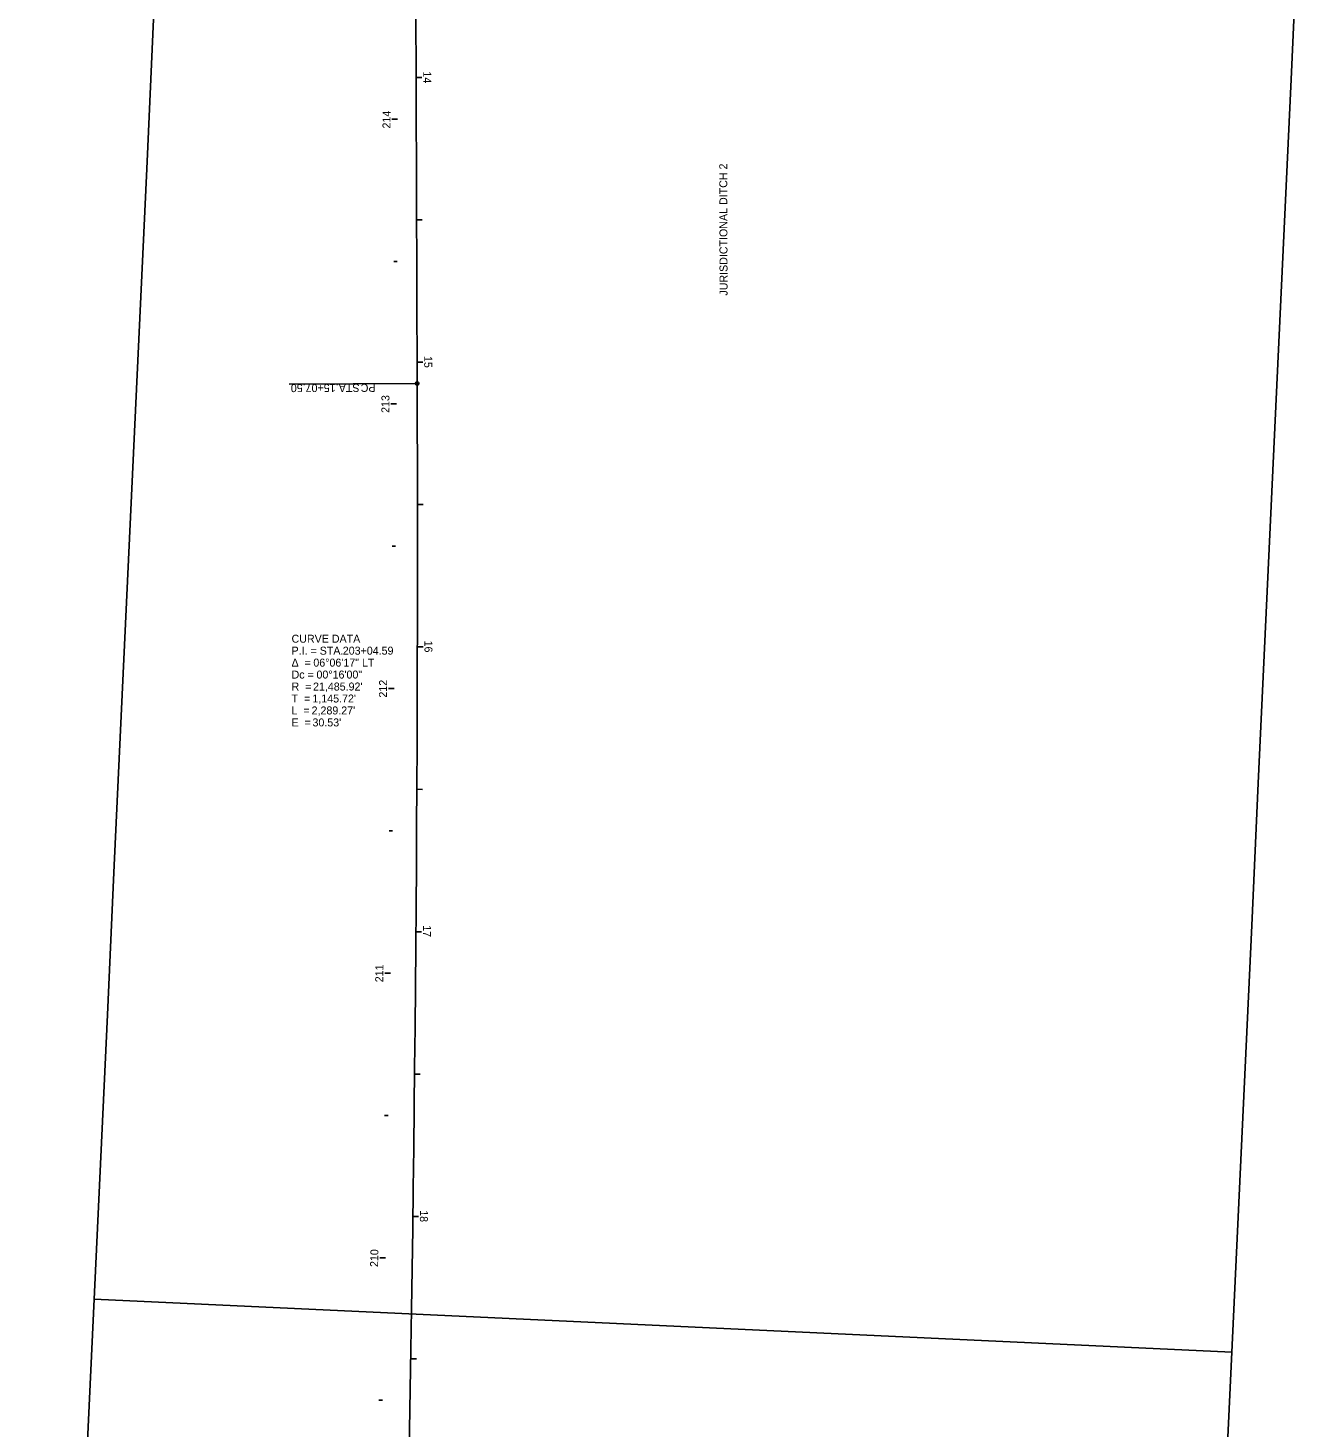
# Model space of a CAD drawing. Extents: x 172043 to 172958, y 249504 to 260295.
# Drawn here: x 172382 to 172828, y 257862.1 to 258353.8 of the extents above; entities that cross this region are included whole.
import ezdxf

# ---------------------------------------------------------------- set-up
doc = ezdxf.new("R2010")
doc.units = 0
for name, color, linetype in [('DR_X_Storm_Sewer', 7, 'Continuous'), ('LT_X_Poles', 7, 'Continuous'), ('PV_X_EOP', 7, 'Continuous'), ('RD_X_Fence', 7, 'Continuous'), ('SC_Scratch1', 7, 'Continuous')]:
    doc.layers.add(name, color=color, linetype=linetype)

msp = doc.modelspace()

# ---------------------------------------------------------------- linework, layer by layer
at = {"layer": 'DR_X_Storm_Sewer'}
for points in [[(172405.19, 257907.39), (172804.75, 257888.81), (172807.08, 257938.76), (172809.4, 257988.7), (172811.72, 258038.65), (172814.04, 258088.6), (172816.37, 258138.54), (172818.69, 258188.49), (172821.01, 258238.43), (172823.34, 258288.38), (172825.66, 258338.33), (172827.98, 258388.27), (172428.41, 258406.85), (172426.09, 258356.91), (172423.77, 258306.96), (172421.44, 258257.02), (172419.12, 258207.07), (172416.8, 258157.12), (172414.48, 258107.18), (172412.15, 258057.23), (172409.83, 258007.29), (172407.51, 257957.34)], [(172381.96, 257407.93), (172781.53, 257389.35), (172783.85, 257439.3), (172786.17, 257489.24), (172788.49, 257539.19), (172790.82, 257589.14), (172793.14, 257639.08), (172795.46, 257689.03), (172797.79, 257738.97), (172800.11, 257788.92), (172802.43, 257838.87), (172804.75, 257888.81), (172405.19, 257907.39), (172402.86, 257857.45), (172400.54, 257807.5), (172398.22, 257757.56), (172395.89, 257707.61), (172393.57, 257657.66), (172391.25, 257607.72), (172388.93, 257557.77), (172386.6, 257507.83), (172384.28, 257457.88)]]:
    msp.add_lwpolyline(points, close=True, dxfattribs=at)
at = {"layer": 'PV_X_EOP'}
for p, q in [((172511.76, 258321.83), (172509.76, 258321.83)), ((172511.63, 258271.83), (172510.43, 258271.84)), ((172511.38, 258221.83), (172509.38, 258221.84)), ((172511.02, 258171.83), (172509.82, 258171.84)), ((172510.54, 258121.84), (172508.54, 258121.86)), ((172509.95, 258071.84), (172508.75, 258071.85)), ((172509.24, 258021.84), (172507.24, 258021.87)), ((172508.41, 257971.85), (172507.21, 257971.87)), ((172507.47, 257921.86), (172505.47, 257921.9)), ((172506.41, 257871.87), (172505.21, 257871.9))]:
    msp.add_line(p, q, dxfattribs=at)
at = {"layer": 'SC_Scratch1'}
for p, q in [((172513.49, 259736.44), (172518.63, 258228.95)), ((172518.27, 258336.45), (172520.27, 258336.45)), ((172518.44, 258286.45), (172520.44, 258286.45)), ((172518.61, 258236.45), (172520.61, 258236.45)), ((172518.63, 258228.95), (172473.63, 258228.79)), ((172518.72, 258186.45), (172520.72, 258186.45)), ((172518.7, 258136.45), (172520.7, 258136.44)), ((172518.52, 258086.45), (172520.52, 258086.44)), ((172518.2, 258036.45), (172520.2, 258036.43)), ((172517.73, 257986.45), (172519.73, 257986.43)), ((172517.11, 257936.45), (172519.11, 257936.43)), ((172517.11, 257936.45), (172519.11, 257936.43)), ((172516.35, 257886.46), (172518.35, 257886.43))]:
    msp.add_line(p, q, dxfattribs=at)
msp.add_circle((172518.63, 258228.95), 0.6, dxfattribs=at)
msp.add_arc((155518.73, 258170.95), 17000, 354.099581, 0.195474, dxfattribs=at)
msp.add_arc((155518.73, 258170.95), 17000, 354.099581, 0.195474, dxfattribs=at)

# ---------------------------------------------------------------- texts
at = {"layer": 'LT_X_Poles'}
msp.add_text('JURISDICTIONAL DITCH 2', height=2.8003, rotation=90.1507, dxfattribs=at).set_placement((172627.65, 258259.85))
at = {"layer": 'PV_X_EOP'}
for s, rotation, p in [('214', 89.9182, (172509.26, 258318.55)), ('213', 89.6516, (172508.86, 258218.65)), ('212', 89.3849, (172508.01, 258118.65)), ('211', 89.1182, (172506.69, 258018.66)), ('210', 88.8516, (172504.9, 257918.64))]:
    msp.add_text(s, height=2.8, rotation=rotation, dxfattribs=at).set_placement(p)
at = {"layer": 'RD_X_Fence'}
for s, p in [('CURVE DATA', (172474.52, 258137.95)), ('P.I. = STA. ', (172474.52, 258133.75)), ('203+04.59', (172492.51, 258133.75)), ('Δ  = ', (172474.52, 258129.55)), ('06°06\'17" LT', (172482.17, 258129.55)), ('Dc = ', (172474.52, 258125.35)), ('R  = ', (172474.52, 258121.15)), ("21,485.92'", (172482.06, 258121.15)), ('00°16\'00"', (172483.27, 258125.35)), ('T  = ', (172474.52, 258116.95)), ("1,145.72'", (172481.84, 258116.95)), ('L  = ', (172474.52, 258112.75)), ("2,289.27'", (172481.56, 258112.75)), ('E  = ', (172474.52, 258108.55)), ("30.53'", (172481.87, 258108.55))]:
    msp.add_text(s, height=2.8, dxfattribs=at).set_placement(p)
at = {"layer": 'SC_Scratch1'}
for s, rotation, p in [('14', 270.1955, (172520.76, 258338.61)), ('15', 270.1955, (172521.1, 258238.64)), ('15+07.50', 180.1955, (172489.97, 258228.81)), (' STA. ', 180.1955, (172499.42, 258228.84)), ('PC', 180.1955, (172504.01, 258228.86)), ('16', 269.8837, (172521.2, 258138.68)), ('17', 269.5467, (172520.72, 258038.73)), ('18', 269.2096, (172519.64, 257938.64))]:
    msp.add_text(s, height=2.8, rotation=rotation, dxfattribs=at).set_placement(p)

doc.saveas('drawing.dxf')
